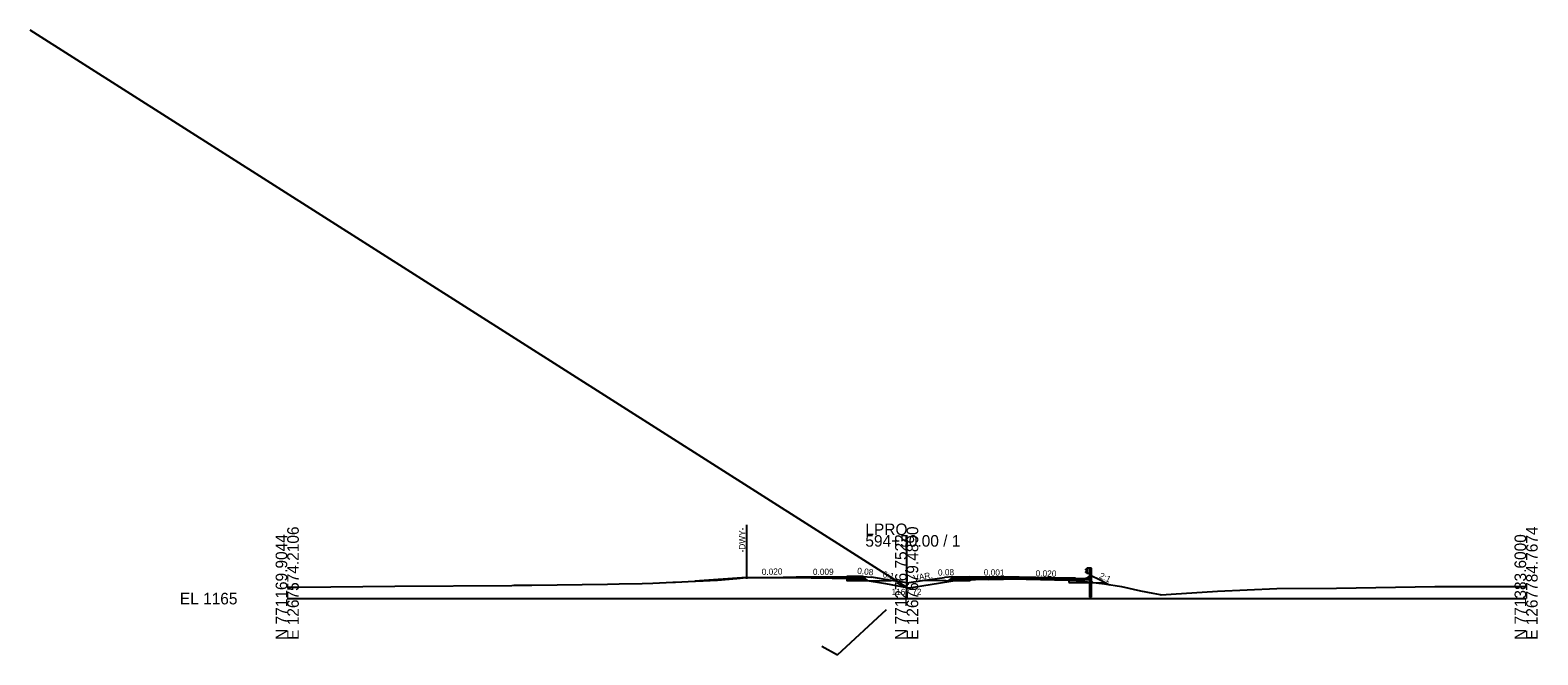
# Model space of a CAD drawing. Extents: x -3833 to 1267678, y -522 to 773248.
# Drawn here: x -62.2 to 302.8, y 5486.4 to 5637.8 of the extents above; entities that cross this region are included whole.
import ezdxf

# ---------------------------------------------------------------- set-up
doc = ezdxf.new("R2010")
doc.units = 0
for name, color, linetype in [('Exist Cross Section Cell', 7, 'Continuous'), ('Exist XS Center Line Elevation Label', 7, 'Continuous'), ('Exist XS Ground Line', 7, 'Continuous'), ('Prop CMT DNC', 7, 'Continuous'), ('Prop CMT Guardrail Graphics', 7, 'Continuous'), ('Prop CMT Pvmt Course 1', 7, 'Continuous'), ('Prop CMT Pvmt Milling', 7, 'Continuous'), ('Prop CMT Shld Paved Course 1', 7, 'Continuous'), ('Prop CMT Shld Paved Course 2', 7, 'Continuous'), ('Prop CMT Shld Paved Course 4', 7, 'Continuous'), ('Prop CMT Slope Grass', 7, 'Continuous'), ('Prop CMT Subgrade Earthwork', 7, 'Continuous'), ('Prop Corridor Mesh Bottom', 7, 'Continuous'), ('Prop XS Ditch Slope Text', 7, 'Continuous'), ('Prop XS Finish Grade', 7, 'Continuous'), ('Prop XS SE Text', 7, 'Continuous'), ('Prop XS Shear Point Element', 7, 'Continuous'), ('Prop XS Shear Point Label', 7, 'Continuous'), ('Scratch_Level_1', 7, 'Continuous'), ('Scratch_Level_5', 7, 'Continuous'), ('Typical Curb CELL', 7, 'Continuous')]:
    doc.layers.add(name, color=color, linetype=linetype)

msp = doc.modelspace()

# ---------------------------------------------------------------- linework, layer by layer
at = {"layer": 'Exist Cross Section Cell'}
for p, q in [((150, 5500), (150, 5515.39)), ((0, 5500), (150, 5500)), ((150, 5500), (300, 5500))]:
    msp.add_line(p, q, dxfattribs=at)
at = {"layer": 'Exist XS Ground Line'}
for p, q in [((0, 5502.81), (2.82, 5502.81)), ((2.82, 5502.81), (26.08, 5502.99)), ((26.08, 5502.99), (54.37, 5503.21)), ((54.37, 5503.21), (54.9, 5503.22)), ((54.37, 5503.21), (54.9, 5503.22)), ((54.9, 5503.22), (59.2, 5503.26)), ((54.9, 5503.22), (59.2, 5503.26)), ((59.2, 5503.26), (77.52, 5503.46)), ((59.2, 5503.26), (77.52, 5503.46)), ((77.52, 5503.46), (80.4, 5503.54)), ((77.52, 5503.46), (80.4, 5503.54)), ((80.4, 5503.54), (85.93, 5503.7)), ((80.4, 5503.54), (85.93, 5503.7)), ((85.93, 5503.7), (88.55, 5503.78)), ((85.93, 5503.7), (88.55, 5503.78)), ((88.55, 5503.78), (93.41, 5503.96)), ((88.55, 5503.78), (93.41, 5503.96)), ((93.41, 5503.96), (94.02, 5503.98)), ((93.41, 5503.96), (94.02, 5503.98)), ((94.02, 5503.98), (97.11, 5504.13)), ((94.02, 5503.98), (97.11, 5504.13)), ((97.11, 5504.13), (100.72, 5504.31)), ((97.11, 5504.13), (100.72, 5504.31)), ((100.72, 5504.31), (104.18, 5504.46)), ((100.72, 5504.31), (104.18, 5504.46)), ((104.18, 5504.46), (108.84, 5504.87)), ((104.18, 5504.46), (108.84, 5504.87)), ((108.84, 5504.87), (111.2, 5505.09)), ((108.84, 5504.87), (111.2, 5505.09)), ((111.2, 5505.09), (115.27, 5505.11)), ((111.2, 5505.09), (115.27, 5505.11)), ((115.27, 5505.11), (122.47, 5505.13)), ((115.27, 5505.11), (122.47, 5505.13)), ((122.47, 5505.13), (131.95, 5504.93)), ((122.47, 5505.13), (131.95, 5504.93)), ((131.95, 5504.93), (136.53, 5504.84)), ((131.95, 5504.93), (136.53, 5504.84)), ((136.53, 5504.84), (137.26, 5504.79)), ((136.53, 5504.84), (137.26, 5504.79)), ((137.26, 5504.79), (138.71, 5504.7)), ((138.71, 5504.7), (139.47, 5504.56)), ((138.71, 5504.7), (139.47, 5504.56)), ((139.47, 5504.56), (144.89, 5503.62)), ((139.47, 5504.56), (144.89, 5503.62)), ((144.89, 5503.62), (150, 5502.72)), ((144.89, 5503.62), (150, 5502.72)), ((150, 5502.72), (150.64, 5502.61)), ((150, 5502.72), (150.64, 5502.61)), ((150.64, 5502.61), (155.73, 5503.44)), ((150.64, 5502.61), (155.73, 5503.44)), ((155.73, 5503.44), (160.73, 5504.22)), ((155.73, 5503.44), (160.73, 5504.22)), ((160.73, 5504.22), (161.64, 5504.38)), ((160.73, 5504.22), (161.64, 5504.38)), ((161.64, 5504.38), (165.63, 5504.57)), ((161.64, 5504.38), (165.63, 5504.57)), ((165.63, 5504.57), (166.63, 5504.59)), ((165.63, 5504.57), (166.63, 5504.59)), ((166.63, 5504.59), (177.2, 5504.8)), ((166.63, 5504.59), (177.2, 5504.8)), ((177.2, 5504.8), (178.92, 5504.75)), ((177.2, 5504.8), (178.92, 5504.75)), ((178.92, 5504.75), (189.77, 5504.43)), ((178.92, 5504.75), (189.77, 5504.43)), ((189.77, 5504.43), (191.06, 5504.33)), ((189.77, 5504.43), (191.06, 5504.33)), ((191.06, 5504.33), (193.17, 5504.18)), ((193.17, 5504.18), (197.94, 5503.54)), ((197.94, 5503.54), (202.02, 5502.97)), ((197.94, 5503.54), (202.02, 5502.97)), ((202.02, 5502.97), (206.6, 5501.86)), ((202.02, 5502.97), (206.6, 5501.86)), ((225.29, 5501.8), (239.61, 5502.41)), ((225.29, 5501.8), (239.61, 5502.41)), ((239.61, 5502.41), (254.05, 5502.55)), ((239.61, 5502.41), (254.05, 5502.55)), ((254.05, 5502.55), (277.89, 5502.97)), ((277.89, 5502.97), (300, 5502.9)), ((206.6, 5501.86), (209.58, 5501.28)), ((206.6, 5501.86), (209.58, 5501.28)), ((209.58, 5501.28), (211.36, 5500.98)), ((209.58, 5501.28), (211.36, 5500.98)), ((211.36, 5500.98), (211.66, 5500.94)), ((211.36, 5500.98), (211.66, 5500.94)), ((211.66, 5500.94), (214.07, 5501.09)), ((211.66, 5500.94), (214.07, 5501.09)), ((214.07, 5501.09), (225.29, 5501.8)), ((214.07, 5501.09), (225.29, 5501.8))]:
    msp.add_line(p, q, dxfattribs=at)
at = {"layer": 'Prop CMT Guardrail Graphics'}
for p, q in [((193.37, 5507.14), (193.52, 5507.24)), ((193.37, 5507), (193.37, 5507.14)), ((193.6, 5506.79), (193.37, 5507)), ((193.37, 5506.5), (193.6, 5506.7)), ((193.37, 5506.36), (193.37, 5506.5)), ((193.52, 5506.26), (193.37, 5506.36)), ((193.52, 5507.24), (193.61, 5507.26)), ((193.61, 5506.24), (193.52, 5506.26)), ((193.6, 5506.7), (193.6, 5506.79)), ((193.61, 5507.34), (193.61, 5506.16)), ((194.28, 5507.34), (193.61, 5507.34)), ((193.61, 5507.26), (193.61, 5506.24)), ((193.61, 5506.16), (194.28, 5506.16)), ((194.28, 5507.34), (194.28, 5504.83)), ((194.77, 5507.34), (194.28, 5507.34)), ((194.28, 5506.16), (194.28, 5507.34)), ((194.77, 5504.84), (194.77, 5507.34)), ((194.28, 5504.83), (194.28, 5500.33)), ((194.77, 5500.33), (194.77, 5504.84)), ((194.28, 5500.33), (194.77, 5500.33))]:
    msp.add_line(p, q, dxfattribs=at)
at = {"layer": 'Prop CMT Pvmt Course 1'}
for p, q in [((111.2, 5505.11), (98.7, 5504.21)), ((111.2, 5505.11), (116.83, 5505.14)), ((116.83, 5505.14), (123.25, 5505.27)), ((123.25, 5505.27), (135.49, 5505.33)), ((123.25, 5505.27), (123.25, 5505.27)), ((135.49, 5505.08), (126.91, 5505.04)), ((135.49, 5505.33), (135.49, 5505.08)), ((135.49, 5505.08), (135.49, 5505.08)), ((177.22, 5505.2), (165.19, 5505.26)), ((165.19, 5505.26), (165.19, 5505.26)), ((165.19, 5505.26), (165.19, 5505.01)), ((165.19, 5505.01), (165.19, 5505.01)), ((165.19, 5505.01), (165.19, 5505.01)), ((165.19, 5505.01), (177.22, 5504.95)), ((189.25, 5504.96), (177.22, 5505.2)), ((177.22, 5505.2), (177.22, 5505.2)), ((177.22, 5504.95), (177.22, 5504.95)), ((177.22, 5504.95), (189.25, 5504.71)), ((189.25, 5504.71), (189.25, 5504.96)), ((189.25, 5504.71), (189.25, 5504.71))]:
    msp.add_line(p, q, dxfattribs=at)
at = {"layer": 'Prop CMT Pvmt Milling'}
for points in [[(189.25, 5504.44), (178.92, 5504.75), (178.92, 5504.75), (177.22, 5504.8), (177.2, 5504.8), (177.2, 5504.8), (166.63, 5504.59), (166.63, 5504.59), (165.63, 5504.57), (165.63, 5504.57), (165.19, 5504.55), (165.19, 5504.55)], [(165.19, 5504.55), (165.19, 5504.55), (165.63, 5504.57), (165.63, 5504.57), (166.63, 5504.59), (166.63, 5504.59), (177.2, 5504.8), (177.2, 5504.8), (177.22, 5504.8), (178.92, 5504.75), (178.92, 5504.75), (189.25, 5504.44)]]:
    msp.add_lwpolyline(points, dxfattribs=at)
at = {"layer": 'Prop CMT Shld Paved Course 1'}
for p, q in [((139.49, 5505.38), (135.49, 5505.33)), ((135.49, 5505.33), (135.49, 5505.33)), ((135.49, 5505.33), (135.49, 5505.08)), ((135.49, 5505.08), (139.73, 5505.13)), ((135.49, 5505.08), (135.49, 5505.08)), ((135.49, 5505.08), (135.49, 5505.08)), ((139.73, 5505.13), (139.49, 5505.38)), ((139.49, 5505.38), (139.49, 5505.38)), ((160.95, 5505.07), (161.19, 5505.31)), ((165.19, 5505.01), (160.95, 5505.07)), ((161.19, 5505.31), (165.19, 5505.26)), ((165.19, 5505.26), (165.19, 5505.01)), ((189.25, 5504.96), (189.25, 5504.71)), ((190.91, 5504.94), (189.25, 5504.96)), ((189.25, 5504.71), (190.91, 5504.69))]:
    msp.add_line(p, q, dxfattribs=at)
at = {"layer": 'Prop CMT Shld Paved Course 2'}
for p, q in [((126.91, 5505.04), (131.95, 5504.93)), ((135.49, 5505.08), (131.95, 5505.06)), ((131.95, 5505.06), (131.95, 5505.06)), ((131.95, 5504.93), (131.95, 5504.93)), ((131.95, 5504.93), (135.49, 5504.86)), ((139.73, 5505.13), (135.49, 5505.08)), ((135.49, 5505.08), (135.49, 5505.08)), ((135.49, 5505.08), (135.49, 5504.74)), ((135.49, 5504.86), (135.49, 5505.08)), ((135.49, 5504.86), (135.49, 5504.86)), ((135.49, 5504.74), (140.06, 5504.8)), ((135.49, 5504.74), (135.49, 5504.74)), ((135.49, 5504.74), (135.49, 5504.74)), ((140.06, 5504.8), (139.73, 5505.13)), ((139.73, 5505.13), (139.73, 5505.13)), ((160.62, 5504.74), (160.95, 5505.07)), ((165.19, 5504.68), (160.62, 5504.74)), ((160.95, 5505.07), (165.19, 5505.01)), ((165.19, 5505.01), (165.19, 5504.68)), ((165.63, 5505.01), (165.19, 5505.01)), ((165.19, 5505.01), (165.19, 5505.01)), ((165.19, 5505.01), (165.19, 5504.68)), ((165.19, 5504.68), (165.19, 5504.68)), ((165.19, 5504.68), (165.19, 5504.68)), ((165.19, 5504.68), (165.63, 5504.68)), ((166.63, 5505), (165.63, 5505.01)), ((165.63, 5505.01), (165.63, 5505.01)), ((165.63, 5504.68), (165.63, 5504.68)), ((165.63, 5504.68), (166.63, 5504.67)), ((177.2, 5504.95), (166.63, 5505)), ((166.63, 5505), (166.63, 5505)), ((166.63, 5504.67), (169.85, 5504.65)), ((169.85, 5504.65), (177.2, 5504.8)), ((169.85, 5504.65), (169.85, 5504.65)), ((177.22, 5504.95), (177.2, 5504.95)), ((177.2, 5504.95), (177.2, 5504.95)), ((177.2, 5504.8), (177.2, 5504.8)), ((177.2, 5504.8), (177.2, 5504.8)), ((177.2, 5504.8), (177.22, 5504.8)), ((178.92, 5504.91), (177.22, 5504.95)), ((177.22, 5504.8), (178.92, 5504.75)), ((189.25, 5504.71), (178.92, 5504.91)), ((178.92, 5504.91), (178.92, 5504.91)), ((178.92, 5504.75), (178.92, 5504.75)), ((178.92, 5504.75), (189.25, 5504.44)), ((189.25, 5504.44), (189.25, 5504.71)), ((189.25, 5504.71), (189.25, 5504.38)), ((189.25, 5504.44), (189.25, 5504.44)), ((189.25, 5504.38), (190.91, 5504.36))]:
    msp.add_line(p, q, dxfattribs=at)
at = {"layer": 'Prop CMT Shld Paved Course 4'}
for p, q in [((135.49, 5504.74), (135.48, 5504.29)), ((135.48, 5504.29), (140.51, 5504.35)), ((135.48, 5504.29), (135.48, 5504.29)), ((135.48, 5504.29), (135.48, 5504.29)), ((139.56, 5504.79), (135.49, 5504.74)), ((135.49, 5504.74), (135.49, 5504.74)), ((140.06, 5504.8), (139.56, 5504.79)), ((139.56, 5504.79), (139.56, 5504.79)), ((140.51, 5504.35), (140.06, 5504.8)), ((140.06, 5504.8), (140.06, 5504.8)), ((160.16, 5504.28), (160.62, 5504.74)), ((165.19, 5504.22), (160.16, 5504.28)), ((160.62, 5504.74), (161.12, 5504.73)), ((161.12, 5504.73), (165.19, 5504.68)), ((165.19, 5504.68), (165.19, 5504.22)), ((189.25, 5504.38), (189.25, 5503.92)), ((189.25, 5503.92), (194.3, 5503.86)), ((190.91, 5504.52), (190.91, 5504.36)), ((194.44, 5504.52), (193.93, 5504.52)), ((195.15, 5503.81), (194.44, 5504.52))]:
    msp.add_line(p, q, dxfattribs=at)
at = {"layer": 'Prop CMT Slope Grass'}
for p, q in [((194.7, 5505.58), (193.93, 5505.2)), ((194.7, 5505.58), (196.68, 5504.59)), ((139.49, 5505.38), (141.49, 5505.22)), ((146.27, 5504.42), (141.49, 5505.22)), ((153.84, 5504.36), (159.19, 5505.15)), ((161.19, 5505.31), (159.19, 5505.15)), ((196.68, 5504.59), (198.24, 5503.81))]:
    msp.add_line(p, q, dxfattribs=at)
at = {"layer": 'Prop CMT Subgrade Earthwork'}
for p, q in [((135.49, 5504.86), (135.48, 5504.29)), ((135.48, 5504.29), (146.27, 5504.42)), ((165.19, 5504.22), (153.84, 5504.36)), ((165.19, 5504.55), (165.19, 5504.22)), ((189.25, 5504.44), (189.25, 5503.92)), ((189.25, 5503.92), (198.24, 5503.81))]:
    msp.add_line(p, q, dxfattribs=at)
at = {"layer": 'Prop Corridor Mesh Bottom'}
for p, q in [((111.2, 5505.03), (111.2, 5504.78)), ((135.49, 5505.33), (135.49, 5505.08)), ((165.19, 5505.26), (165.19, 5505.01)), ((189.25, 5504.96), (189.25, 5504.71))]:
    msp.add_line(p, q, dxfattribs=at)
at = {"layer": 'Prop XS Finish Grade'}
for p, q in [((141.49, 5505.22), (141.49, 5505.22)), ((150, 5503.8), (146.27, 5504.42)), ((150, 5503.8), (153.84, 5504.36)), ((150, 5503.8), (150, 5503.8)), ((150, 5503.8), (150, 5503.8)), ((198.24, 5503.81), (199.11, 5503.37))]:
    msp.add_line(p, q, dxfattribs=at)
at = {"layer": 'Prop XS Shear Point Element'}
msp.add_line((111.2, 5517.84), (111.2, 5504.78), dxfattribs=at)
at = {"layer": 'Scratch_Level_1'}
msp.add_line((150, 5502.72), (-62.25, 5637.78), dxfattribs=at)
at = {"layer": 'Scratch_Level_5'}
for p, q in [((133.26, 5486.36), (145.12, 5497.39)), ((129.47, 5488.47), (133.26, 5486.36))]:
    msp.add_line(p, q, dxfattribs=at)
at = {"layer": 'Typical Curb CELL'}
for p, q in [((190.91, 5504.94), (190.91, 5504.94)), ((190.91, 5504.52), (190.91, 5504.93)), ((193.93, 5504.52), (190.91, 5504.52)), ((190.92, 5504.94), (193.25, 5504.85)), ((191.15, 5504.67), (191.24, 5504.79)), ((191.27, 5504.68), (191.15, 5504.67)), ((191.24, 5504.79), (191.27, 5504.68)), ((191.92, 5504.62), (191.98, 5504.74)), ((192.08, 5504.66), (191.92, 5504.62)), ((191.98, 5504.74), (192.08, 5504.66)), ((192.4, 5504.67), (192.49, 5504.79)), ((192.52, 5504.68), (192.4, 5504.67)), ((192.49, 5504.79), (192.52, 5504.68)), ((193.17, 5504.62), (193.23, 5504.74)), ((193.33, 5504.66), (193.17, 5504.62)), ((193.23, 5504.74), (193.33, 5504.66)), ((193.25, 5504.85), (193.93, 5505.2)), ((193.74, 5504.86), (193.76, 5504.77)), ((193.9, 5504.82), (193.74, 5504.86)), ((193.76, 5504.77), (193.9, 5504.82)), ((193.93, 5504.52), (193.93, 5505.2))]:
    msp.add_line(p, q, dxfattribs=at)
for centre in [(191, 5504.76), (191.04, 5504.89), (191.41, 5504.81), (191.47, 5504.63), (191.52, 5504.6), (191.56, 5504.72), (191.63, 5504.72), (191.68, 5504.75), (191.73, 5504.64), (191.92, 5504.68), (192.13, 5504.66), (192.15, 5504.71), (192.16, 5504.77), (192.21, 5504.63), (192.31, 5504.67), (192.4, 5504.68), (192.52, 5504.63), (192.72, 5504.63), (192.77, 5504.6), (192.81, 5504.72), (192.93, 5504.75), (192.98, 5504.64), (193.17, 5504.68), (193.2, 5504.58), (193.38, 5504.66), (193.4, 5504.71), (193.65, 5504.68), (193.77, 5504.63), (193.87, 5504.91)]:
    msp.add_circle(centre, 0.00802, dxfattribs=at)
msp.add_arc((190.92, 5504.93), 0.0104, 87.952, 180, dxfattribs=at)

# ---------------------------------------------------------------- texts
at = {"layer": 'Exist Cross Section Cell'}
for s, p in [('E 1267574.2106', (2.8, 5490)), ('E 1267679.4890', (152.8, 5490)), ('E 1267784.7674', (302.8, 5490)), ('N 771169.9044', (0, 5490)), ('N 771276.7522', (150, 5490)), ('N 771383.6000', (300, 5490))]:
    msp.add_text(s, height=2.8, rotation=90, dxfattribs=at).set_placement(p)
for s, p in [('LPRO', (140, 5515.39)), ('594+50.00 / 1', (140, 5512.59)), ('EL 1165', (-26, 5498.6))]:
    msp.add_text(s, height=2.8, dxfattribs=at).set_placement(p)
at = {"layer": 'Exist XS Center Line Elevation Label'}
msp.add_text('1167.72', height=1.5, dxfattribs=at).set_placement((146.34, 5500.88))
at = {"layer": 'Prop CMT DNC'}
for p in [(70.91, 5503.39), (123.25, 5505.27), (135.49, 5505.33), (135.49, 5505.33), (139.49, 5505.38), (141.49, 5505.22), (159.19, 5505.15), (161.19, 5505.31), (165.19, 5505.26), (165.19, 5505.26), (177.22, 5505.2), (189.25, 5504.96), (189.25, 5504.96), (193, 5504.85), (216.92, 5501.27)]:
    msp.add_text('X', height=0.00025, dxfattribs=at).set_placement(p)
at = {"layer": 'Prop XS Ditch Slope Text'}
for s, rotation, p in [('6:1', 346.8183, (144.09, 5505.24)), ('VAR.', 9.5559, (151.77, 5504.22)), ('2:1', 335.81, (196.49, 5505.01))]:
    msp.add_text(s, height=1.5, rotation=rotation, dxfattribs=at).set_placement(p)
at = {"layer": 'Prop XS SE Text'}
for s, rotation, p in [('0.020', 1.397, (114.92, 5505.72)), ('0.009', 0.2693, (127.3, 5505.73)), ('0.08', 354.0053, (137.97, 5506.02)), ('0.08', 1.397, (157.6, 5505.57)), ('0.001', 359.3542, (168.67, 5505.61)), ('0.020', 358.8542, (181.22, 5505.4))]:
    msp.add_text(s, height=1.5, rotation=rotation, dxfattribs=at).set_placement(p)
at = {"layer": 'Prop XS Shear Point Label'}
msp.add_text('-DWY-', height=1.5, rotation=90, dxfattribs=at).set_placement((110.91, 5511.19))

doc.saveas('drawing.dxf')
